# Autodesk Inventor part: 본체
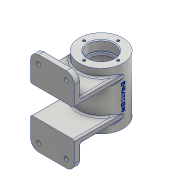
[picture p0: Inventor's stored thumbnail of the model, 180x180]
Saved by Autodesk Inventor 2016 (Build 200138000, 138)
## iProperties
Created: 2017-02
Part Number: 본체
Material: 알루미늄 6061
Document SubType Name: Modeling
Designer: CAMTIC
Density: 2.7 g/cm^3
Appearance: 알루미늄 - 평지
Mass: 354.768 g
Surface Area: 422.772 cm^2
Volume: 131.396 cm^3
Author: CAMTIC
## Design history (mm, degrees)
sketch "스케치1"
  geometry: L1 (27, 52)-(-27, 52); L2 (-27, -52)-(27, -52); L3 (27, -17)-(-27, -17); L4 (27, 17)-(-27, 17); L5 (-27, 52)-(-27, 17); L6 (-27, -17)-(-27, -52); L7 (27, -52)-(27, -17); L8 (27, 17)-(27, 52); 1 further point
  constraints: 16 end point, 5 parallel, 2 perpendicular, 1 horizontal
  dimensions: "d0" = 54 distance of L2.start L2.end; "d1" = 104 distance of L1.end L2.start
extrude "돌출1" new body sketch "스케치1" distance "d4" = 8; taper "d5" = 0 deg
sketch "스케치2"
  geometry: L1 (0, 0)-(0, 60); C1 r 27 at (0, 60)
  constraints: 2 end point, 1 centre point, 1 coincident, 1 vertical
  dimensions: "d6" = 60 distance of L1.start L1.end; "d7" = 54 diameter of C1
extrude "돌출2" join sketch "스케치2" stored distance "d8" = 70; taper "d9" = 0 deg
sketch "스케치3"
  geometry: L1 (0, 0)-(60, 0); L2 (33, -35)-(87, -35) reference; L3 (60, -35)-(60, 35); L4 (60, -35)-(76, -35); L5 (76, -35)-(76, -23); L6 (76, -23)-(74, -23); L7 (74, -23)-(74, -20); L8 (74, -20)-(82, -20); L9 (87, -35)-(87, 35) reference; L10 (82, -20)-(82, 20); L11 (82, 20)-(74, 20); L12 (74, 20)-(74, 23); L13 (74, 23)-(76, 23); L14 (76, 23)-(76, 35); L15 (87, 35)-(33, 35) reference; L16 (76, 35)-(60, 35)
  constraints: 26 end point, 6 perpendicular, 3 horizontal, 2 point on line, 2 vertical, 1 collinear, 1 midpoint
  dimensions: "d10" = 60 distance of L1.start L1.end; "d11" = 16 distance of L3.start L4.end; "d12" = 12 distance of L4.end L5.end; "d13" = 2 distance of L5.end L6.end; "d14" = 3 distance of L6.end L7.end; "d15" = 8 distance of L7.end L8.end; "d16" = 40 distance of L8.end L10.end; "d17" = 8 distance of L10.end L11.end; "d18" = 3 distance of L11.end L12.end; "d19" = 2 distance of L12.end L13.end
revolve "회전1" sketch "스케치3" stored, may be unused: angle "d20" = 90 deg
node "작업 평면1"
sketch "스케치4"
  geometry: L1 (27, 35)-(-27, 35) reference; L2 (0, 35)-(0, 10); C1 r 5 at (0, 10); 1 further point
  constraints: 2 end point, 1 centre point, 1 coincident, 1 midpoint, 1 vertical
  dimensions: "d22" = 25 distance of L2.start L2.end; "d23" = 10 diameter of C1
extrude "돌출3" join sketch "스케치4" stored distance "d24" = 0; taper "d25" = 0 deg
sketch "스케치5"
  geometry: L1 (-27, 17)-(27, 17) reference; L2 (-27, 17)-(-27, 25); L3 (-27, 25)-(27, 25); L4 (27, 25)-(27, 17); L5 (27, 17)-(-27, 17); L6 (27, -17)-(27, -25); L7 (27, -52)-(27, -17) reference; L8 (27, -25)-(-27, -25); L9 (27, -17)-(-27, -17) reference; L10 (-27, -25)-(-27, -17); L11 (-27, -17)-(27, -17); 1 further point
  constraints: 16 end point, 5 perpendicular, 1 collinear, 1 point on line, 1 vertical
  dimensions: "d26" = 8 distance of L1.start L2.end; "d27" = 8 distance of L6.start L6.end
extrude "돌출4" join sketch "스케치5" stored distance "d28" = 70; taper "d29" = 0 deg
sketch "스케치6"
  geometry: A1 r 21 centre (0, 0) between (0, 21) and (21, 0); 3 further points
  constraints: 4 point on circle, 1 centre point
  dimensions: "d30" = 42 diameter of A1
hole "구멍1" sketch "스케치6" at (0, 21), (21, 0), (0, -21), (-21, 0) diameter "d31" = 3.242; stored, may be unused: countersink angle "d35" = 90 deg, drill point angle "d37" = 118 deg; dims "d32" = 8, "d33" = 4, "d34" = 2, "d36" = 10
sketch "스케치7" dims "d38" = 42
  geometry: C1 r 1.621 at (0, 21) reference; C2 r 1.621 at (21, 0) reference; C3 r 1.621 at (0, -21) reference; 7 further points
  constraints: 4 coincident, 1 horizontal alignment, 2 other
hole "구멍2" sketch "스케치7" at (0, 21), (21, 0), (0, -21), (-21, 0) diameter "d39" = 3.242; stored, may be unused: countersink angle "d43" = 90 deg, drill point angle "d45" = 118 deg; dims "d40" = 8, "d41" = 4, "d42" = 2, "d44" = 10
sketch "스케치8"
  geometry: 2 further points
hole "구멍3" sketch "스케치8" at (0, 0) diameter "d46" = 5.188; stored, may be unused: countersink angle "d50" = 90 deg, drill point angle "d52" = 118 deg; dims "d47" = 12, "d48" = 4, "d49" = 2, "d51" = 16
node "작업 평면2"
sketch "스케치10"
  geometry: L1 (0, 0)-(-16.339, -25.16); L2 (0, 0)-(30, 0); 2 further points
  constraints: 4 end point, 1 equal length, 1 horizontal
  dimensions: "d89" = 30 distance of L1.start L1.end; "d90" = 123 deg angle of L1 L2
sketch "스케치13"
  geometry: L1 (27, 52)-(-27, 52) reference; L2 (0, 52)-(0, -52); L3 (-27, -52)-(27, -52) reference; L4 (17, 52)-(17, -52); L5 (-17, 52)-(-17, -52); L6 (-27, 0)-(27, 0); L7 (-27, 42)-(27, 42); L8 (-27, -42)-(27, -42); L9 (-12.5, 39.402)-(-17, 36.804); L10 (-17, 36.804)-(-21.5, 39.402); L11 (-21.5, 39.402)-(-21.5, 44.598); L12 (-21.5, 44.598)-(-17, 47.196); L13 (-17, 47.196)-(-12.5, 44.598); L14 (-12.5, 44.598)-(-12.5, 39.402); L15 (21.5, 39.402)-(17, 36.804); L16 (17, 36.804)-(12.5, 39.402); L17 (12.5, 39.402)-(12.5, 44.598); L18 (12.5, 44.598)-(17, 47.196); L19 (17, 47.196)-(21.5, 44.598); L20 (21.5, 44.598)-(21.5, 39.402); L21 (21.5, -44.598)-(17, -47.196); L22 (17, -47.196)-(12.5, -44.598); L23 (12.5, -44.598)-(12.5, -39.402); L24 (12.5, -39.402)-(17, -36.804); L25 (17, -36.804)-(21.5, -39.402); L26 (21.5, -39.402)-(21.5, -44.598); L27 (-12.5, -44.598)-(-17, -47.196); L28 (-17, -47.196)-(-21.5, -44.598); L29 (-21.5, -44.598)-(-21.5, -39.402); L30 (-21.5, -39.402)-(-17, -36.804); L31 (-17, -36.804)-(-12.5, -39.402); L32 (-12.5, -39.402)-(-12.5, -44.598); C1 r 4.5 at (-17, 42); C2 r 4.5 at (17, 42); C3 r 4.5 at (17, -42); C4 r 4.5 at (-17, -42); 9 further points
  constraints: 60 end point, 6 midpoint, 5 point on line, 4 centre point, 4 parallel, 3 coincident, 1 horizontal, 52 other
  dimensions: "d68" = 17 distance between parallel lines of L2 L4; "d69" = 17 distance between parallel lines of L2 L5; "d70" = 42 distance between parallel lines of L6 L7; "d71" = 42 distance between parallel lines of L6 L8; "d84" = 9 diameter of C1; "d85" = 9 diameter of C2; "d86" = 9 diameter of C3; "d87" = 9 diameter of C4
extrude "돌출6" cut sketch "스케치13" distance "d76" = 3; taper "d77" = 0 deg
sketch "스케치15"
  geometry: C1 r 2.5 at (-17, 42); C2 r 2.5 at (17, 42); C3 r 2.5 at (17, -42); C4 r 2.5 at (-17, -42); 1 further point
  constraints: 4 centre point
  dimensions: "d78" = 5 diameter of C1; "d79" = 5 diameter of C2; "d80" = 5 diameter of C3; "d81" = 5 diameter of C4
extrude "돌출7" cut sketch "스케치15" stored distance "d82" = 3; taper "d83" = 0 deg
node "작업 평면4"
node "작업 평면5"
sketch "스케치17"
  geometry: C1 r 6 at (0, 0); 1 further point
  constraints: 1 centre point
  dimensions: "d91" = 12 diameter of C1
extrude "돌출8" join sketch "스케치17" stored distance "d92" = 3; taper "d93" = 0 deg
sketch "스케치18"
  geometry: 2 further points
hole "구멍5" sketch "스케치18" at (0, 0) diameter "d94" = 5.188; stored, may be unused: countersink angle "d98" = 90 deg, drill point angle "d100" = 118 deg; dims "d95" = 12, "d96" = 4, "d97" = 2, "d99" = 16
sketch "스케치19"
  geometry: L1 (87, 35)-(33, 35) reference; L2 (87, 35)-(87, 0); L3 (87, -35)-(87, 35) reference; L4 (87, 0)-(60, 0); L5 (62.402, 16.049)-(62.402, -17.134); L6 (62.402, -17.134)-(57.598, -17.134); L7 (57.598, -17.134)-(57.598, 16.049); L8 (57.598, 16.049)-(62.402, 16.049); 1 further point
  constraints: 4 end point, 1 midpoint, 1 perpendicular, 2 other
  dimensions: "d101" = 35 distance of L1.start L2.end (derived); "d102" = 27 distance of L2.end L4.end
feature "엠보싱1" sketch "스케치19" dims "d0" = 54, "d1" = 104, "d11" = 16, "d12" = 12, "d13" = 2, "d14" = 3, "d15" = 8, "d16" = 40, "d17" = 8, "d18" = 3, "d19" = 2, "d103" = 0.5, "d104" = 0
fillet "모깎기1" dims "d105" = 2
fillet "모깎기2" dims "d106" = 10
fillet "모깎기3" dims "d107" = 3
fillet "모깎기4" dims "d108" = 0.3
chamfer "모따기1" distance "d109" = 1; stored, may be unused: second distance "d110" = 2, angle "d111" = 45 deg
chamfer "모따기2" distance "d112" = 1; stored, may be unused: second distance "d113" = 2, angle "d114" = 45 deg
node "솔리드1"
other parameters: "d21" = 92, "d55" = -35
